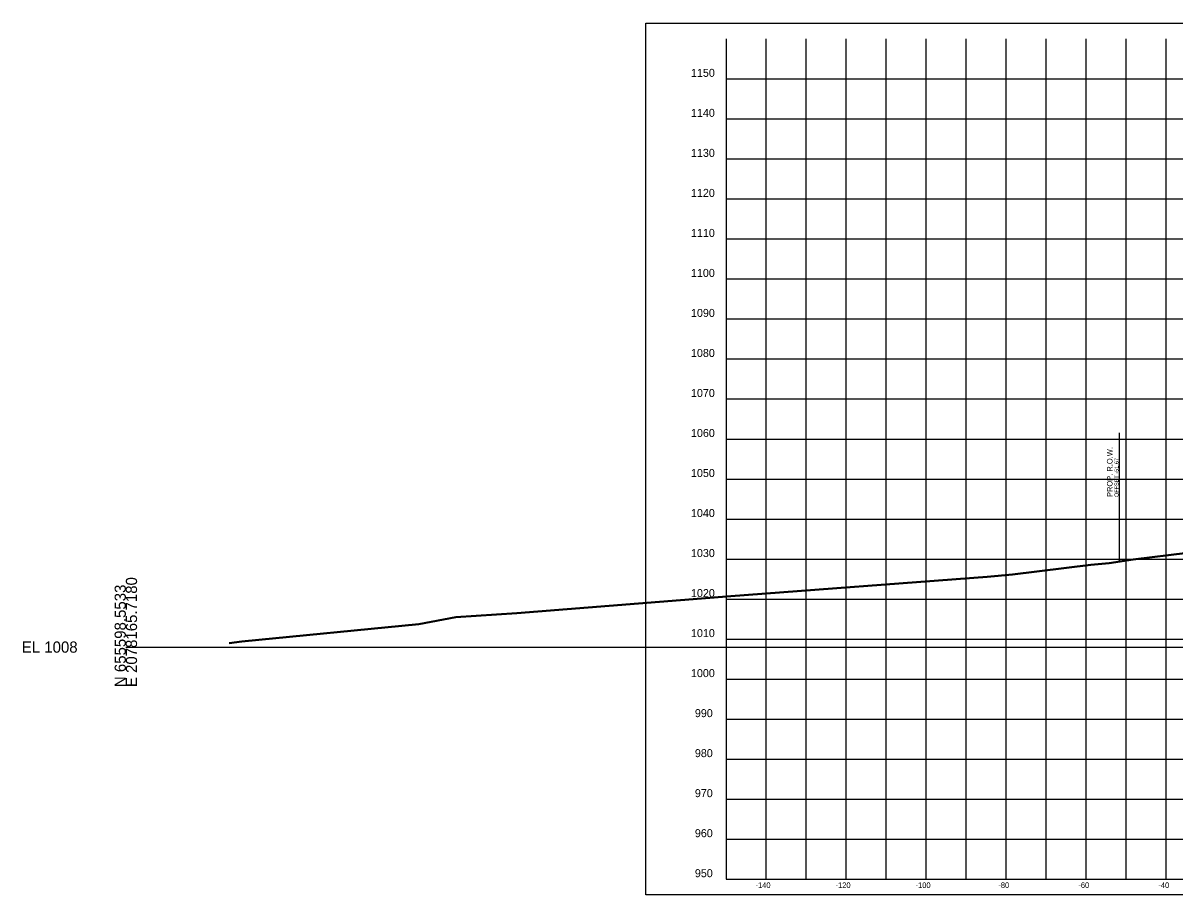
# Model space of a CAD drawing. Extents: x 5868 to 6683, y 2883 to 19120.
# Drawn here: x 5868.1 to 6156, y 6383.1 to 6601 of the extents above; entities that cross this region are included whole.
import ezdxf

# ---------------------------------------------------------------- set-up
doc = ezdxf.new("R2010")
doc.units = 0
for name, color, linetype in [('DESIGN - ROW - Right-of-Way and Easement Labels', 7, 'Continuous'), ('DESIGN - ROW - Right-of-Way Linework', 7, 'Continuous'), ('DESIGN - SHEET - Corner Text', 7, 'Continuous'), ('DESIGN - SHEET - Light Grid', 7, 'Continuous'), ('DESIGN - SHEET - Linework', 7, 'Continuous'), ('DESIGN - SHEET - Plot Shape', 7, 'Continuous'), ('SURVEY - GROUND - Bottom of Topsoil Layer', 7, 'Continuous'), ('SURVEY - GROUND - Top of Ground', 7, 'Continuous')]:
    doc.layers.add(name, color=color, linetype=linetype)

msp = doc.modelspace()

# ---------------------------------------------------------------- linework, layer by layer
at = {"layer": 'DESIGN - ROW - Right-of-Way Linework'}
msp.add_line((6142.12, 6466.57), (6142.12, 6498.57), dxfattribs=at)
at = {"layer": 'DESIGN - SHEET - Light Grid'}
msp.add_line((5893.78, 6445.07), (6193.78, 6445.07), dxfattribs=at)
at = {"layer": 'DESIGN - SHEET - Linework'}
for p, q in [((6053.78, 6387.07), (6053.78, 6597.07)), ((6063.78, 6387.07), (6063.78, 6597.07)), ((6073.78, 6387.07), (6073.78, 6597.07)), ((6083.78, 6387.07), (6083.78, 6597.07)), ((6093.78, 6387.07), (6093.78, 6597.07)), ((6103.78, 6387.07), (6103.78, 6597.07)), ((6113.78, 6387.07), (6113.78, 6597.07)), ((6123.78, 6387.07), (6123.78, 6597.07)), ((6133.78, 6387.07), (6133.78, 6597.07)), ((6143.78, 6387.07), (6143.78, 6597.07)), ((6153.78, 6387.07), (6153.78, 6597.07)), ((6043.78, 6587.07), (6343.78, 6587.07)), ((6043.78, 6577.07), (6343.78, 6577.07)), ((6043.78, 6567.07), (6343.78, 6567.07)), ((6043.78, 6557.07), (6343.78, 6557.07)), ((6043.78, 6547.07), (6343.78, 6547.07)), ((6043.78, 6537.07), (6343.78, 6537.07)), ((6043.78, 6527.07), (6343.78, 6527.07)), ((6043.78, 6517.07), (6343.78, 6517.07)), ((6043.78, 6507.07), (6343.78, 6507.07)), ((6043.78, 6497.07), (6343.78, 6497.07)), ((6043.78, 6487.07), (6343.78, 6487.07)), ((6043.78, 6477.07), (6343.78, 6477.07)), ((6043.78, 6467.07), (6343.78, 6467.07)), ((6043.78, 6457.07), (6343.78, 6457.07)), ((6043.78, 6447.07), (6343.78, 6447.07)), ((6043.78, 6437.07), (6343.78, 6437.07)), ((6043.78, 6427.07), (6343.78, 6427.07)), ((6043.78, 6417.07), (6343.78, 6417.07)), ((6043.78, 6407.07), (6343.78, 6407.07)), ((6043.78, 6397.07), (6343.78, 6397.07))]:
    msp.add_line(p, q, dxfattribs=at)
msp.add_lwpolyline([(6043.78, 6597.07), (6043.78, 6387.07), (6343.78, 6387.07), (6343.78, 6597.07)], dxfattribs=at)
at = {"layer": 'DESIGN - SHEET - Plot Shape'}
msp.add_lwpolyline([(6023.78, 6601.01), (6363.78, 6601.01), (6363.78, 6383.13), (6023.78, 6383.13)], close=True, dxfattribs=at)
at = {"layer": 'SURVEY - GROUND - Bottom of Topsoil Layer'}
for p, q in [((6139.56, 6465.92), (6145.52, 6466.85)), ((6145.52, 6466.85), (6159.13, 6468.53)), ((6109.07, 6462.53), (6115.41, 6463.15)), ((6115.41, 6463.15), (6134.97, 6465.58)), ((6134.97, 6465.58), (6139.56, 6465.92)), ((6044.95, 6457.7), (6109.07, 6462.53)), ((5991.5, 6453.47), (6044.95, 6457.7)), ((5967.01, 6450.75), (5976.25, 6452.44)), ((5976.25, 6452.44), (5991.5, 6453.47)), ((5922.78, 6446.39), (5967.01, 6450.75)), ((5919.57, 6446), (5922.78, 6446.39))]:
    msp.add_line(p, q, dxfattribs=at)
at = {"layer": 'SURVEY - GROUND - Top of Ground'}
msp.add_lwpolyline([(5919.57, 6446.25), (5922.78, 6446.64), (5967.01, 6451), (5976.25, 6452.69), (5991.5, 6453.72), (6044.95, 6457.95), (6109.07, 6462.78), (6115.41, 6463.4), (6134.97, 6465.83), (6139.56, 6466.17), (6145.52, 6467.1), (6159.13, 6468.78)], dxfattribs=at)

# ---------------------------------------------------------------- texts
at = {"layer": 'DESIGN - ROW - Right-of-Way and Easement Labels'}
for s, height, p in [('PROP. R.O.W.', 1.4, (6140.37, 6482.57)), ('OFFSET -51.67', 1, (6141.87, 6482.57))]:
    msp.add_text(s, height=height, rotation=90, dxfattribs=at).set_placement(p)
at = {"layer": 'DESIGN - SHEET - Corner Text'}
for s, height, p in [('1150', 2, (6035.03, 6587.57)), ('1140', 2, (6035.03, 6577.57)), ('1130', 2, (6035.03, 6567.57)), ('1120', 2, (6035.03, 6557.57)), ('1110', 2, (6035.03, 6547.57)), ('1100', 2, (6035.03, 6537.57)), ('1090', 2, (6035.03, 6527.57)), ('1080', 2, (6035.03, 6517.57)), ('1070', 2, (6035.03, 6507.57)), ('1060', 2, (6035.03, 6497.57)), ('1050', 2, (6035.03, 6487.57)), ('1040', 2, (6035.03, 6477.57)), ('1030', 2, (6035.03, 6467.57)), ('1020', 2, (6035.03, 6457.57)), ('1010', 2, (6035.03, 6447.57)), ('1000', 2, (6035.03, 6437.57)), ('990', 2, (6036, 6427.57)), ('980', 2, (6036, 6417.57)), ('970', 2, (6036, 6407.57)), ('960', 2, (6036, 6397.57)), ('950', 2, (6036, 6387.57)), ('-140', 1.4, (6051.16, 6384.87)), ('-120', 1.4, (6071.16, 6384.87)), ('-100', 1.4, (6091.16, 6384.87)), ('-80', 1.4, (6111.84, 6384.87)), ('-60', 1.4, (6131.84, 6384.87)), ('-40', 1.4, (6151.84, 6384.87))]:
    msp.add_text(s, height=height, dxfattribs=at).set_placement(p)
at = {"layer": 'DESIGN - SHEET - Light Grid'}
for s, p in [('N 655598.5533', (5893.78, 6435.07)), ('E 2078165.7180', (5896.58, 6435.07))]:
    msp.add_text(s, height=2.8, rotation=90, dxfattribs=at).set_placement(p)
msp.add_text('EL 1008', height=2.8, dxfattribs=at).set_placement((5867.78, 6443.67))

doc.saveas('drawing.dxf')
